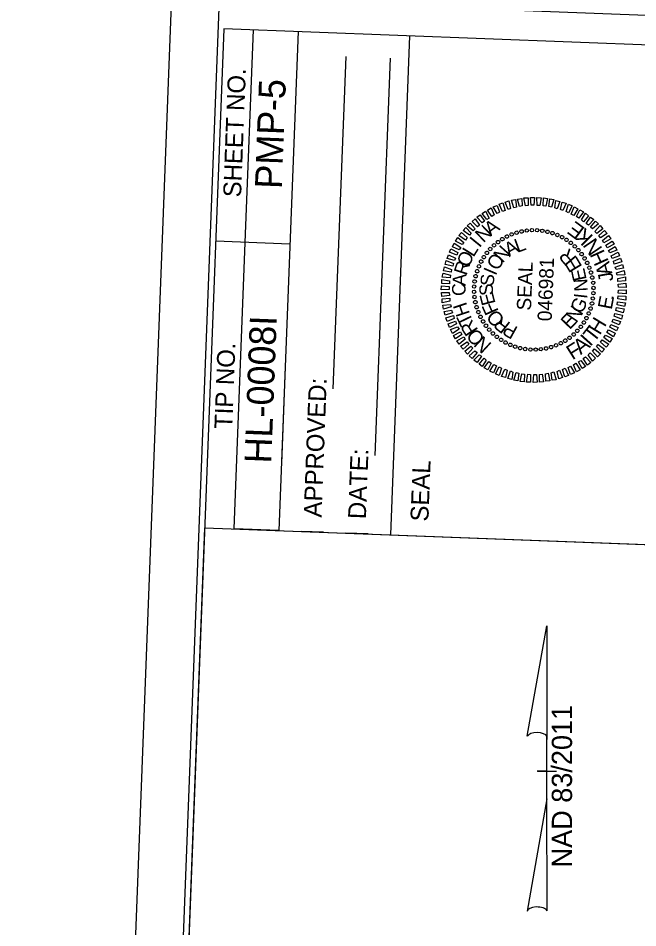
# Model space of a CAD drawing. Extents: x 2097098 to 2098257, y 686470 to 688528.
# Drawn here: x 2097098.5 to 2097358.6, y 687799 to 688180.8 of the extents above; entities that cross this region are included whole.
import ezdxf

# ---------------------------------------------------------------- set-up
doc = ezdxf.new("R2010")
doc.units = 0
for name, color, linetype in [('Default', 7, 'Continuous'), ('Sheet Data Field CELL', 7, 'Continuous'), ('Sheet Layout Plan Border', 7, 'Continuous'), ('Sheet Plan CELL', 7, 'Continuous'), ('Sheet Plot Border Inside CELL', 7, 'Continuous'), ('Sheet Plot Border Outside CELL', 7, 'Continuous'), ('Sheet Title CELL', 7, 'Continuous')]:
    doc.layers.add(name, color=color, linetype=linetype)

msp = doc.modelspace()

# ---------------------------------------------------------------- linework, layer by layer
at = {"layer": 'Default'}
for p, q in [((2097309.79, 688091.35), (2097309.79, 688091.35)), ((2097312, 688091.67), (2097312, 688091.67)), ((2097314.16, 688091.88), (2097314.16, 688091.88)), ((2097316.36, 688091.85), (2097316.36, 688091.85)), ((2097318.55, 688091.62), (2097318.55, 688091.62)), ((2097320.69, 688091.18), (2097320.69, 688091.18)), ((2097301.71, 688088.11), (2097301.71, 688088.11)), ((2097303.65, 688089.18), (2097303.65, 688089.18)), ((2097305.64, 688090.11), (2097305.64, 688090.11)), ((2097307.66, 688090.83), (2097307.66, 688090.83)), ((2097322.77, 688090.65), (2097322.77, 688090.65)), ((2097324.84, 688089.87), (2097324.84, 688089.87)), ((2097326.8, 688088.9), (2097326.8, 688088.9)), ((2097328.71, 688087.82), (2097328.71, 688087.82)), ((2097296.64, 688084), (2097296.64, 688084)), ((2097298.2, 688085.49), (2097298.2, 688085.49)), ((2097299.91, 688086.93), (2097299.91, 688086.93)), ((2097330.47, 688086.5), (2097330.47, 688086.5)), ((2097332.16, 688085.09), (2097332.16, 688085.09)), ((2097333.65, 688083.53), (2097333.65, 688083.53)), ((2097293.91, 688080.55), (2097293.91, 688080.55)), ((2097295.23, 688082.3), (2097295.23, 688082.3)), ((2097335.09, 688081.82), (2097335.09, 688081.82)), ((2097336.27, 688080.03), (2097336.27, 688080.03)), ((2097291.86, 688076.68), (2097291.86, 688076.68)), ((2097292.84, 688078.64), (2097292.84, 688078.64)), ((2097337.35, 688078.08), (2097337.35, 688078.08)), ((2097338.27, 688076.1), (2097338.27, 688076.1)), ((2097290.55, 688072.52), (2097290.55, 688072.52)), ((2097291.08, 688074.61), (2097291.08, 688074.61)), ((2097339, 688074.07), (2097339, 688074.07)), ((2097339.51, 688071.95), (2097339.51, 688071.95)), ((2097289.88, 688068.2), (2097289.88, 688068.2)), ((2097290.12, 688070.39), (2097290.12, 688070.39)), ((2097339.83, 688069.73), (2097339.83, 688069.73)), ((2097289.85, 688066), (2097289.85, 688066)), ((2097314.95, 688066.79), (2097314.95, 688066.79)), ((2097340.01, 688065.37), (2097340.01, 688065.37)), ((2097340.05, 688067.57), (2097340.05, 688067.57)), ((2097290.07, 688063.84), (2097290.07, 688063.84)), ((2097290.38, 688061.62), (2097290.38, 688061.62)), ((2097339.35, 688061.05), (2097339.35, 688061.05)), ((2097339.78, 688063.18), (2097339.78, 688063.18)), ((2097290.9, 688059.5), (2097290.9, 688059.5)), ((2097291.62, 688057.47), (2097291.62, 688057.47)), ((2097338.04, 688056.89), (2097338.04, 688056.89)), ((2097338.82, 688058.96), (2097338.82, 688058.96)), ((2097292.55, 688055.49), (2097292.55, 688055.49)), ((2097293.63, 688053.54), (2097293.63, 688053.54)), ((2097335.99, 688053.02), (2097335.99, 688053.02)), ((2097337.06, 688054.93), (2097337.06, 688054.93)), ((2097294.81, 688051.75), (2097294.81, 688051.75)), ((2097296.24, 688050.04), (2097296.24, 688050.04)), ((2097333.25, 688049.57), (2097333.25, 688049.57)), ((2097334.67, 688051.27), (2097334.67, 688051.27)), ((2097297.73, 688048.48), (2097297.73, 688048.48)), ((2097299.43, 688047.07), (2097299.43, 688047.07)), ((2097301.18, 688045.75), (2097301.18, 688045.75)), ((2097328.19, 688045.46), (2097328.19, 688045.46)), ((2097329.99, 688046.64), (2097329.99, 688046.64)), ((2097331.69, 688048.08), (2097331.69, 688048.08)), ((2097303.09, 688044.67), (2097303.09, 688044.67)), ((2097305.06, 688043.7), (2097305.06, 688043.7)), ((2097307.13, 688042.92), (2097307.13, 688042.92)), ((2097309.21, 688042.39), (2097309.21, 688042.39)), ((2097311.34, 688041.95), (2097311.34, 688041.95)), ((2097313.54, 688041.72), (2097313.54, 688041.72)), ((2097315.74, 688041.69), (2097315.74, 688041.69)), ((2097317.9, 688041.9), (2097317.9, 688041.9)), ((2097320.11, 688042.22), (2097320.11, 688042.22)), ((2097322.23, 688042.74), (2097322.23, 688042.74)), ((2097324.26, 688043.46), (2097324.26, 688043.46)), ((2097326.25, 688044.39), (2097326.25, 688044.39)), ((2097312.22, 687879.48), (2097320.42, 687925.83)), ((2097320.47, 687925.83), (2097320.42, 687925.83)), ((2097320.47, 687925.83), (2097320.42, 687925.83)), ((2097320.47, 687925.83), (2097320.47, 687878.03)), ((2097320.47, 687853.23), (2097320.47, 687879.43)), ((2097320.47, 687878.03), (2097320.47, 687879.38)), ((2097316.47, 687864.83), (2097316.42, 687864.83)), ((2097320.02, 687864.83), (2097316.47, 687864.83)), ((2097316.52, 687864.83), (2097324.52, 687864.83)), ((2097320.47, 687853.23), (2097312.12, 687805.98)), ((2097320.52, 687806.18), (2097320.47, 687853.23))]:
    msp.add_line(p, q, dxfattribs=at)
for points in [[(2097301.75, 688099.72), (2097300.36, 688102.72), (2097301.99, 688103.31), (2097302.87, 688100.17)], [(2097304.13, 688100.52), (2097302.95, 688103.62), (2097304.52, 688104.11), (2097305.2, 688100.98)], [(2097306.56, 688101.23), (2097305.54, 688104.47), (2097307.2, 688104.71), (2097307.62, 688101.54)], [(2097308.98, 688101.74), (2097308.15, 688104.92), (2097309.87, 688105.16), (2097310.04, 688102)], [(2097311.4, 688102.1), (2097310.82, 688105.37), (2097312.53, 688105.46), (2097312.61, 688102.25)], [(2097313.81, 688102.3), (2097313.53, 688105.57), (2097315.24, 688105.6), (2097315.01, 688102.36)], [(2097316.31, 688102.26), (2097316.28, 688105.51), (2097317.98, 688105.45), (2097317.51, 688102.21)], [(2097318.81, 688102.11), (2097319.03, 688105.36), (2097320.67, 688105.19), (2097320, 688101.97)], [(2097321.19, 688101.77), (2097321.62, 688104.96), (2097323.31, 688104.69), (2097322.38, 688101.48)], [(2097323.73, 688101.27), (2097324.25, 688104.36), (2097325.93, 688103.94), (2097324.76, 688100.83)], [(2097326.1, 688100.53), (2097326.87, 688103.61), (2097328.5, 688103.19), (2097327.13, 688100.09)], [(2097328.47, 688099.69), (2097329.49, 688102.75), (2097331.01, 688102.05), (2097329.5, 688099.1)], [(2097295.22, 688096.36), (2097293.21, 688098.89), (2097294.7, 688099.79), (2097296.19, 688096.93)], [(2097297.32, 688097.58), (2097295.52, 688100.3), (2097297.05, 688101.2), (2097298.34, 688098.24)], [(2097299.56, 688098.8), (2097297.92, 688101.66), (2097299.5, 688102.25), (2097300.54, 688099.36)], [(2097330.63, 688098.61), (2097331.9, 688101.66), (2097333.42, 688100.85), (2097331.71, 688098.07)], [(2097332.89, 688097.52), (2097334.25, 688100.32), (2097335.77, 688099.51), (2097333.82, 688096.88)], [(2097334.99, 688096.24), (2097336.6, 688098.98), (2097337.96, 688097.93), (2097335.86, 688095.4)], [(2097289.53, 688091.53), (2097287.01, 688093.68), (2097288.25, 688094.83), (2097290.31, 688092.45)], [(2097291.35, 688093.26), (2097289.08, 688095.5), (2097290.32, 688096.65), (2097292.17, 688093.98)], [(2097293.21, 688094.94), (2097291.05, 688097.32), (2097292.44, 688098.32), (2097294.24, 688095.6)], [(2097336.93, 688094.66), (2097338.74, 688097.3), (2097340.15, 688096.29), (2097337.86, 688093.98)], [(2097338.77, 688093.09), (2097340.82, 688095.61), (2097342.08, 688094.47), (2097339.65, 688092.36)], [(2097287.91, 688089.69), (2097285.23, 688091.64), (2097286.38, 688092.9), (2097288.64, 688090.61)], [(2097340.61, 688091.27), (2097342.75, 688093.74), (2097343.85, 688092.45), (2097341.37, 688090.44)], [(2097342.29, 688089.55), (2097344.57, 688091.67), (2097345.73, 688090.42), (2097342.95, 688088.58)], [(2097284.91, 688085.8), (2097282.11, 688087.26), (2097283.02, 688088.72), (2097285.54, 688086.73)], [(2097286.33, 688087.7), (2097283.5, 688089.56), (2097284.6, 688090.82), (2097286.97, 688088.77)], [(2097343.76, 688087.5), (2097346.24, 688089.55), (2097347.24, 688088.16), (2097344.38, 688086.52)], [(2097345.19, 688085.54), (2097347.81, 688087.29), (2097348.71, 688085.96), (2097345.75, 688084.42)], [(2097282.63, 688081.33), (2097279.53, 688082.6), (2097280.18, 688083.98), (2097283.03, 688082.47)], [(2097283.67, 688083.55), (2097280.77, 688084.91), (2097281.53, 688086.43), (2097284.26, 688084.62)], [(2097346.35, 688083.29), (2097349.12, 688085.04), (2097349.86, 688083.46), (2097346.92, 688082.32)], [(2097281.65, 688079.12), (2097278.58, 688079.99), (2097279.14, 688081.52), (2097282.04, 688080.16)], [(2097347.47, 688081.1), (2097350.33, 688082.59), (2097350.97, 688081.02), (2097347.88, 688079.98)], [(2097348.44, 688078.86), (2097351.38, 688080.05), (2097351.93, 688078.53), (2097348.69, 688077.6)], [(2097280.26, 688074.22), (2097277.08, 688074.79), (2097277.39, 688076.43), (2097280.45, 688075.41)], [(2097280.91, 688076.75), (2097277.68, 688077.37), (2097278.14, 688079.05), (2097281.2, 688077.79)], [(2097349.14, 688076.38), (2097352.18, 688077.42), (2097352.57, 688075.85), (2097349.45, 688075.32)], [(2097279.77, 688071.84), (2097276.53, 688072.16), (2097276.89, 688073.8), (2097280.01, 688073.03)], [(2097349.7, 688073.96), (2097352.89, 688074.89), (2097353.17, 688073.17), (2097349.91, 688072.9)], [(2097350.16, 688071.54), (2097353.38, 688072.22), (2097353.47, 688070.56), (2097350.26, 688070.33)], [(2097279.38, 688066.95), (2097276.12, 688066.82), (2097276.23, 688068.47), (2097279.47, 688068.15)], [(2097279.52, 688069.34), (2097276.27, 688069.47), (2097276.39, 688071.12), (2097279.62, 688070.54)], [(2097350.36, 688069.13), (2097353.58, 688069.56), (2097353.72, 688067.85), (2097350.47, 688067.92)], [(2097279.53, 688064.44), (2097276.31, 688064.01), (2097276.18, 688065.72), (2097279.43, 688065.65)], [(2097350.38, 688064.23), (2097353.62, 688064.1), (2097353.51, 688062.45), (2097350.28, 688063.03)], [(2097350.52, 688066.62), (2097353.78, 688066.75), (2097353.66, 688065.1), (2097350.42, 688065.42)], [(2097279.74, 688062.03), (2097276.51, 688061.35), (2097276.43, 688063.01), (2097279.64, 688063.24)], [(2097280.2, 688059.61), (2097277.01, 688058.68), (2097276.73, 688060.4), (2097279.99, 688060.67)], [(2097350.13, 688061.73), (2097353.37, 688061.41), (2097353.01, 688059.77), (2097349.88, 688060.54)], [(2097280.76, 688057.19), (2097277.71, 688056.15), (2097277.32, 688057.72), (2097280.45, 688058.25)], [(2097348.99, 688056.82), (2097352.22, 688056.2), (2097351.76, 688054.52), (2097348.7, 688055.78)], [(2097349.64, 688059.35), (2097352.82, 688058.78), (2097352.51, 688057.14), (2097349.44, 688058.16)], [(2097281.46, 688054.71), (2097278.51, 688053.52), (2097277.97, 688055.04), (2097281.21, 688055.97)], [(2097282.43, 688052.47), (2097279.57, 688050.98), (2097278.93, 688052.56), (2097282.02, 688053.59)], [(2097348.25, 688054.45), (2097351.32, 688053.58), (2097350.76, 688052.05), (2097347.86, 688053.41)], [(2097283.54, 688050.28), (2097280.77, 688048.53), (2097280.03, 688050.11), (2097282.98, 688051.25)], [(2097284.71, 688048.03), (2097282.09, 688046.28), (2097281.19, 688047.61), (2097284.15, 688049.15)], [(2097346.23, 688050.02), (2097349.13, 688048.66), (2097348.37, 688047.14), (2097345.64, 688048.95)], [(2097347.26, 688052.24), (2097350.37, 688050.97), (2097349.71, 688049.59), (2097346.87, 688051.1)], [(2097286.13, 688046.07), (2097283.65, 688044.02), (2097282.66, 688045.41), (2097285.52, 688047.05)], [(2097343.57, 688045.87), (2097346.4, 688044.01), (2097345.3, 688042.75), (2097342.93, 688044.8)], [(2097344.99, 688047.77), (2097347.79, 688046.31), (2097346.88, 688044.85), (2097344.36, 688046.84)], [(2097287.61, 688044.02), (2097285.32, 688041.9), (2097284.17, 688043.15), (2097286.94, 688044.99)], [(2097289.29, 688042.3), (2097287.14, 688039.83), (2097286.04, 688041.12), (2097288.52, 688043.13)], [(2097340.37, 688042.04), (2097342.89, 688039.89), (2097341.64, 688038.74), (2097339.58, 688041.12)], [(2097341.99, 688043.88), (2097344.67, 688041.93), (2097343.52, 688040.67), (2097341.25, 688042.96)], [(2097291.12, 688040.48), (2097289.07, 688037.96), (2097287.82, 688039.1), (2097290.25, 688041.21)], [(2097292.96, 688038.91), (2097291.16, 688036.27), (2097289.75, 688037.28), (2097292.04, 688039.59)], [(2097294.9, 688037.33), (2097293.3, 688034.59), (2097291.94, 688035.64), (2097294.04, 688038.17)], [(2097336.69, 688038.63), (2097338.85, 688036.25), (2097337.46, 688035.25), (2097335.66, 688037.97)], [(2097338.55, 688040.31), (2097340.82, 688038.07), (2097339.57, 688036.92), (2097337.72, 688039.59)], [(2097297.01, 688036.05), (2097295.65, 688033.25), (2097294.13, 688034.06), (2097296.08, 688036.69)], [(2097299.27, 688034.96), (2097298, 688031.91), (2097296.48, 688032.72), (2097298.19, 688035.5)], [(2097301.43, 688033.88), (2097300.41, 688030.82), (2097298.89, 688031.52), (2097300.4, 688034.47)], [(2097328.15, 688033.86), (2097329.53, 688030.85), (2097327.91, 688030.26), (2097327.03, 688033.4)], [(2097330.33, 688034.77), (2097331.97, 688031.91), (2097330.4, 688031.32), (2097329.36, 688034.21)], [(2097332.58, 688035.99), (2097334.38, 688033.27), (2097332.84, 688032.37), (2097331.55, 688035.33)], [(2097334.68, 688037.21), (2097336.68, 688034.68), (2097335.2, 688033.78), (2097333.71, 688036.64)], [(2097303.8, 688033.04), (2097303.03, 688029.96), (2097301.39, 688030.38), (2097302.76, 688033.48)], [(2097306.17, 688032.3), (2097305.65, 688029.21), (2097303.97, 688029.63), (2097305.14, 688032.74)], [(2097308.7, 688031.8), (2097308.28, 688028.61), (2097306.59, 688028.88), (2097307.51, 688032.09)], [(2097311.09, 688031.46), (2097310.87, 688028.21), (2097309.22, 688028.38), (2097309.9, 688031.6)], [(2097313.59, 688031.31), (2097313.61, 688028.06), (2097311.91, 688028.12), (2097312.39, 688031.36)], [(2097316.09, 688031.27), (2097316.36, 688028), (2097314.66, 688027.97), (2097314.89, 688031.21)], [(2097318.5, 688031.47), (2097319.07, 688028.2), (2097317.37, 688028.11), (2097317.29, 688031.32)], [(2097320.91, 688031.83), (2097321.74, 688028.65), (2097320.03, 688028.41), (2097319.85, 688031.57)], [(2097323.33, 688032.34), (2097324.36, 688029.1), (2097322.7, 688028.86), (2097322.27, 688032.03)], [(2097325.76, 688033.05), (2097326.95, 688029.95), (2097325.38, 688029.46), (2097324.69, 688032.59)]]:
    msp.add_lwpolyline(points, close=True, dxfattribs=at)
for centre, major_axis in [((2097305.63, 688090.07), (-0.267, 0.668)), ((2097307.7, 688090.79), (-0.208, 0.689)), ((2097309.82, 688091.33), (-0.147, 0.705)), ((2097311.98, 688091.69), (-0.085, 0.715)), ((2097314.16, 688091.85), (-0.023, 0.72)), ((2097316.35, 688091.83), (0.04, 0.719)), ((2097318.52, 688091.61), (0.103, 0.713)), ((2097320.67, 688091.2), (0.164, 0.701)), ((2097322.78, 688090.61), (0.225, 0.684)), ((2097299.92, 688086.87), (-0.431, 0.576)), ((2097301.73, 688088.1), (-0.379, 0.612)), ((2097303.64, 688089.17), (-0.325, 0.643)), ((2097324.83, 688089.84), (0.284, 0.662)), ((2097326.8, 688088.89), (0.34, 0.635)), ((2097328.68, 688087.77), (0.394, 0.602)), ((2097330.46, 688086.5), (0.445, 0.566)), ((2097296.66, 688083.95), (-0.525, 0.493)), ((2097298.23, 688085.48), (-0.48, 0.537)), ((2097332.12, 688085.07), (0.493, 0.525)), ((2097333.64, 688083.5), (0.537, 0.48)), ((2097292.84, 688078.64), (-0.635, 0.34)), ((2097293.96, 688080.52), (-0.602, 0.394)), ((2097295.24, 688082.29), (-0.566, 0.445)), ((2097335.03, 688081.81), (0.576, 0.431)), ((2097336.26, 688080), (0.612, 0.379)), ((2097291.9, 688076.66), (-0.662, 0.284)), ((2097337.33, 688078.09), (0.643, 0.325)), ((2097338.23, 688076.1), (0.668, 0.267)), ((2097290.53, 688072.51), (-0.701, 0.164)), ((2097291.12, 688074.62), (-0.684, 0.225)), ((2097338.96, 688074.04), (0.689, 0.208)), ((2097339.5, 688071.92), (0.705, 0.147)), ((2097289.91, 688068.18), (-0.719, 0.04)), ((2097290.12, 688070.36), (-0.713, 0.103)), ((2097339.85, 688069.76), (0.715, 0.085)), ((2097340.02, 688067.57), (0.72, 0.023)), ((2097289.88, 688066), (-0.72, -0.023)), ((2097290.05, 688063.81), (-0.715, -0.085)), ((2097339.99, 688065.39), (0.719, -0.04)), ((2097290.4, 688061.65), (-0.705, -0.147)), ((2097290.94, 688059.53), (-0.689, -0.208)), ((2097339.37, 688061.06), (0.701, -0.164)), ((2097339.77, 688063.21), (0.713, -0.103)), ((2097291.66, 688057.47), (-0.668, -0.267)), ((2097338, 688056.91), (0.662, -0.284)), ((2097338.77, 688058.95), (0.684, -0.225)), ((2097292.56, 688055.48), (-0.643, -0.325)), ((2097293.63, 688053.57), (-0.612, -0.379)), ((2097335.94, 688053.05), (0.602, -0.394)), ((2097337.05, 688054.93), (0.635, -0.34)), ((2097294.87, 688051.76), (-0.576, -0.431)), ((2097296.25, 688050.07), (-0.537, -0.48)), ((2097297.78, 688048.5), (-0.493, -0.525)), ((2097331.67, 688048.09), (0.48, -0.537)), ((2097333.23, 688049.62), (0.525, -0.493)), ((2097334.66, 688051.28), (0.566, -0.445)), ((2097299.44, 688047.07), (-0.445, -0.566)), ((2097301.22, 688045.8), (-0.394, -0.602)), ((2097303.1, 688044.68), (-0.34, -0.635)), ((2097326.26, 688044.4), (0.325, -0.643)), ((2097328.17, 688045.47), (0.379, -0.612)), ((2097329.97, 688046.7), (0.431, -0.576)), ((2097305.07, 688043.73), (-0.284, -0.662)), ((2097307.12, 688042.96), (-0.225, -0.684)), ((2097309.22, 688042.37), (-0.164, -0.701)), ((2097311.37, 688041.96), (-0.103, -0.713)), ((2097313.55, 688041.74), (-0.04, -0.719)), ((2097315.74, 688041.72), (0.023, -0.72)), ((2097317.92, 688041.88), (0.085, -0.715)), ((2097320.08, 688042.24), (0.147, -0.705)), ((2097322.2, 688042.78), (0.208, -0.689)), ((2097324.26, 688043.5), (0.267, -0.668))]:
    msp.add_ellipse(centre, major_axis=major_axis, ratio=0.999708, dxfattribs=at)
for centre, start_param, end_param in [((2097316.36, 687878.99), 0.216388, 2.908219), ((2097316.36, 687805.82), 0.201328, 3.141593)]:
    msp.add_ellipse(centre, major_axis=(4.23, -0.03), ratio=0.461098, start_param=start_param, end_param=end_param, dxfattribs=at)
at = {"layer": 'Sheet Layout Plan Border'}
msp.add_lwpolyline([(2098218.44, 687728.94), (2098179.19, 686705.44), (2097129.59, 686735.95), (2097169.5, 687776.57), (2097171.49, 687828.53), (2097176.8, 687966.96), (2097416.72, 687957.76), (2097421.45, 688081.2), (2098143.33, 688053.51), (2098131.01, 687732.3)], close=True, dxfattribs=at)
at = {"layer": 'Sheet Plan CELL'}
for p, q in [((2097184.83, 688176.38), (2097127.35, 686677.47)), ((2098234.06, 688136.14), (2097184.83, 688176.38))]:
    msp.add_line(p, q, dxfattribs=at)
at = {"layer": 'Sheet Plot Border Inside CELL'}
msp.add_lwpolyline([(2098173.2, 686483.77), (2098237.04, 688148.49), (2097182.82, 688188.93), (2097118.98, 686524.2)], close=True, dxfattribs=at)
at = {"layer": 'Sheet Plot Border Outside CELL'}
msp.add_lwpolyline([(2098192.69, 686470.01), (2098257.21, 688152.23), (2097163.01, 688194.19), (2097098.5, 686511.97)], close=True, dxfattribs=at)
at = {"layer": 'Sheet Title CELL'}
for p, q in [((2097193.79, 688086.71), (2097197.21, 688175.91)), ((2097215.97, 688175.19), (2097207.94, 687965.76)), ((2097254.86, 687963.97), (2097262.89, 688173.39)), ((2097230.78, 688025.25), (2097236.14, 688164.81)), ((2097248.37, 687997.28), (2097254.77, 688164.09)), ((2097212.56, 688085.99), (2097181.41, 688087.19)), ((2097189.18, 687966.48), (2097193.79, 688086.71)), ((2097210.59, 688034.56), (2097209.03, 687993.91)), ((2097176.8, 687966.96), (2097365.88, 687959.71)), ((2097207.94, 687965.76), (2097189.18, 687966.48)), ((2097226.72, 687965.04), (2097217.33, 687965.4)), ((2097245.47, 687964.33), (2097236.1, 687964.68))]:
    msp.add_line(p, q, dxfattribs=at)

# ---------------------------------------------------------------- texts
at = {"layer": 'Default'}
for s, height, rotation, p in [('A', 5.95, 36.4209, (2097296.84, 688089.1)), ('E', 6.29, 143.2967, (2097336.74, 688092.57)), ('N', 5.99, 43.6226, (2097293.78, 688086.26)), ('K', 6.36, 135.0128, (2097340.23, 688089.16)), ('I', 5.98, 50.8238, (2097292.15, 688084.17)), ('A', 5.89, 29.564, (2097304.57, 688080.49)), ('L', 5.79, 20.2045, (2097308.09, 688082.31)), ('N', 6.36, 124.287, (2097343.96, 688084.06)), ('L', 5.93, 58.0246, (2097289.59, 688080.22)), ('N', 5.99, 48.2803, (2097301.86, 688077.74)), ('R', 5.99, 130.2851, (2097333.23, 688080.19)), ('H', 6.27, 114.303, (2097346.51, 688078.77)), ('O', 5.85, 65.2249, (2097287.58, 688075.89)), ('O', 5.94, 57.6372, (2097299.73, 688074.47)), ('046981', 5.998, 87.8037, (2097322.45, 688053.52)), ('E', 5.96, 120.9278, (2097335.44, 688076.56)), ('R', 5.75, 72.4248, (2097286.7, 688072.57)), ('I', 5.83, 66.9933, (2097298.96, 688072.5)), ('SEAL', 5.998, 87.8037, (2097313.76, 688058.03)), ('E', 5.74, 102.2155, (2097337.18, 688071.19)), ('A', 6.15, 105.4627, (2097347.98, 688073.78)), ('A', 5.64, 86.824, (2097286.34, 688068.38)), ('S', 5.64, 85.7041, (2097298.09, 688068.23)), ('J', 6.08, 100.2049, (2097348.48, 688070.72)), ('C', 5.66, 94.0236, (2097286.49, 688064.42)), ('S', 5.67, 95.0593, (2097298, 688064.63)), ('N', 5.65, 92.8601, (2097337.59, 688066.22)), ('E', 5.77, 104.4148, (2097298.92, 688061.15)), ('I', 5.65, 83.5049, (2097337.31, 688062.88)), ('E', 6.04, 78.8614, (2097347.62, 688058.25)), ('H', 5.82, 108.4232, (2097288.19, 688056.75)), ('F', 5.89, 113.7707, (2097300.3, 688057.89)), ('G', 5.86, 64.7939, (2097335.17, 688056.4)), ('.', 6, 85.9707, (2097348.42, 688062.36)), ('O', 5.98, 132.4849, (2097303.12, 688054.48)), ('E', 5.99, 46.0806, (2097329.96, 688049.8)), ('N', 5.95, 55.4377, (2097332.77, 688052.69)), ('T', 5.91, 115.6235, (2097289.72, 688053.44)), ('R', 5.97, 122.8242, (2097291.79, 688049.96)), ('R', 5.93, 141.8433, (2097305.5, 688052.64)), ('H', 6.3, 58.677, (2097342.66, 688047.5)), ('O', 5.99, 130.0254, (2097294.75, 688046.39)), ('P', 5.84, 151.2026, (2097308.64, 688050.92)), ('T', 6.36, 51.8768, (2097340.19, 688044.36)), ('N', 5.96, 137.2272, (2097297.56, 688043.98)), ('A', 6.35, 39.2346, (2097334.67, 688039.38)), ('I', 6.37, 48.0749, (2097338.64, 688042.73)), ('F', 6.29, 32.2179, (2097331.17, 688037.17)), ('NAD 83/2011', 8.5, 90, (2097330.99, 687824.36))]:
    msp.add_text(s, height=height, rotation=rotation, dxfattribs=at).set_placement(p)
at = {"layer": 'Sheet Data Field CELL'}
for s, height, p in [('SHEET NO.', 7.512, (2097192.03, 688105.54)), ('PMP-5', 11.268, (2097209.12, 688109.04)), ('HL-0008I', 11.268, (2097204.7, 687993.81)), ('TIP NO.', 7.512, (2097188.34, 688008.3)), ('APPROVED:', 7.512, (2097225.82, 687971.17)), ('DATE:', 7.512, (2097244.45, 687970.46)), ('SEAL', 7.512, (2097270.65, 687969.45))]:
    msp.add_text(s, height=height, rotation=87.8037, dxfattribs=at).set_placement(p)

doc.saveas('drawing.dxf')
